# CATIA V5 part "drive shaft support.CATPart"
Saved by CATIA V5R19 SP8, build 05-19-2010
Part number: drive shaft support
Bounding box of the stored display mesh (mm): x -21.546 to 21.546, y 153.1 to 173.1, z -10.482 to 11.169
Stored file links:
  G:\EU_thinkMotion\CFAO_2010\MMS_groupe1\MMS_groupe1\A reprendre\gduval\CFAO kinematic ok\drive shaft support.CATPart
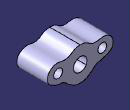
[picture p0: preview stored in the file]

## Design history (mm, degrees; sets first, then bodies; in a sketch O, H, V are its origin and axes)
Body1 (main body)
  Plane1 to Plane3: stored without definition
  Point1: stored without definition
  Line1: type PtDir, RefPoint Point1, Direction Plane3, Start -20, End 20
  Point2: type OnPlane, Support Plane1, H -14.5, V 2.2, Direction (-1, 0, 0)
  Point3: type OnPlane, Support Plane1, H 14.5, V 2.2, Direction (-1, 0, 0)
  Line2: type Normal, RefPoint Point2, RefSkin Plane1, Start -20, End 20
  Line3: type Normal, RefPoint Point3, RefSkin Plane1, Start -20, End 20
  Plane4: type Offset, RefPlane Plane1, Offset 1
  Sketch1 on Plane4, origin (0, 153.1, 0), H (-1, 0, 0), V (0, 0, 1)
    spline S1 through (0, 11.1691) (2.8674, 10.8507) (4.5654, 10.0016) (6.688, 8.5158) (10.5086, 7.6667) (15.2844, 8.3035) (19.7417, 6.4993) (21.5459, 2.8908) (20.4846, -1.1421) (17.9376, -2.8402) (14.966, -4.2199) (11.4638, -4.5383) (9.3412, -5.8119) (8.0677, -7.0854) (6.0512, -8.8897) (4.0348, -9.8448) (1.5939, -10.4816) (0, -10.4816)
    spline S2 through (0, 11.1691) (-2.8674, 10.8507) (-4.5654, 10.0016) (-6.688, 8.5158) (-10.5086, 7.6667) (-15.2844, 8.3035) (-19.7417, 6.4993) (-21.5459, 2.8908) (-20.4846, -1.1421) (-17.9376, -2.8402) (-14.966, -4.2199) (-11.4638, -4.5383) (-9.3412, -5.8119) (-8.0677, -7.0854) (-6.0512, -8.8897) (-4.0348, -9.8448) (-1.5939, -10.4816) (0, -10.4816)
    point P1 (0, 11.1691)
    point P2 (0, -10.4816)
    point P3 (0, -10.4816)
    point P4 (0, 11.1691)
    point P5 (1.5939, -10.4816)
    point P6 (-1.5939, -10.4816)
    point P7 (4.0348, -9.8448)
    point P8 (-4.0348, -9.8448)
    point P9 (6.0512, -8.8897)
    point P10 (-6.0512, -8.8897)
    point P11 (8.0677, -7.0854)
    point P12 (-8.0677, -7.0854)
    point P13 (9.3412, -5.8119)
    point P14 (-9.3412, -5.8119)
    point P15 (11.4638, -4.5383)
    point P16 (-11.4638, -4.5383)
    point P17 (14.966, -4.2199)
    point P18 (-14.966, -4.2199)
    point P19 (17.9376, -2.8402)
    point P20 (-17.9376, -2.8402)
    point P21 (20.4846, -1.1421)
    point P22 (-20.4846, -1.1421)
    point P23 (21.5459, 2.8908)
    point P24 (-21.5459, 2.8908)
    point P25 (19.7417, 6.4993)
    point P26 (-19.7417, 6.4993)
    point P27 (15.2844, 8.3035)
    point P28 (-15.2844, 8.3035)
    point P29 (10.5086, 7.6667)
    point P30 (-10.5086, 7.6667)
    point P31 (6.688, 8.5158)
    point P32 (-6.688, 8.5158)
    point P33 (4.5654, 10.0016)
    point P34 (-4.5654, 10.0016)
    point P35 (2.8674, 10.8507)
    point P36 (-2.8674, 10.8507)
    coincidence: P1 V, P2 V, P1 P4, P2 P3
    symmetry: S1 S2 V, P2 P3 V, P1 P4 V, P5 P6 V, P7 P8 V, P9 P10 V, P11 P12 V, P13 P14 V, P15 P16 V, P17 P18 V, P19 P20 V, P21 P22 V, P23 P24 V, P25 P26 V, P27 P28 V, P29 P30 V, P31 P32 V, P33 P34 V, P35 P36 V
  Pad1: profile Sketch1, direction (0, 1, 0), length 20
  Sketch2 on start face of Pad1, origin (-14.5, 153.1, 2.2), H (1, 0, 0), V (0, 0, 1)
    point P1 (0, 0)
    intersected point E1 (0, 0) from Line3
    coincidence: E1 P1
  Hole1: placed by Sketch2, at (-14.5, 153.1, 2.2) direction (0, 1, 0), diameter 6, through (limit type 6)
  Sketch3 on start face of Pad1, origin (14.5, 153.1, 2.2), H (1, 0, 0), V (0, 0, 1)
    point P1 (0, 0)
    intersected point E1 (0, 0) from Line2
    coincidence: E1 P1
  Hole2: placed by Sketch3, at (14.5, 153.1, 2.2) direction (0, 1, 0), diameter 6, through (limit type 6)
  Sketch4 on end face of Pad1, origin (0, 173.1, 0), H (1, 0, 0), V (0, 0, -1)
    point P1 (0, 0)
  Hole3: placed by Sketch4, at (0, 173.1, 0) direction (0, -1, 0), diameter 9, through (limit type 6)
